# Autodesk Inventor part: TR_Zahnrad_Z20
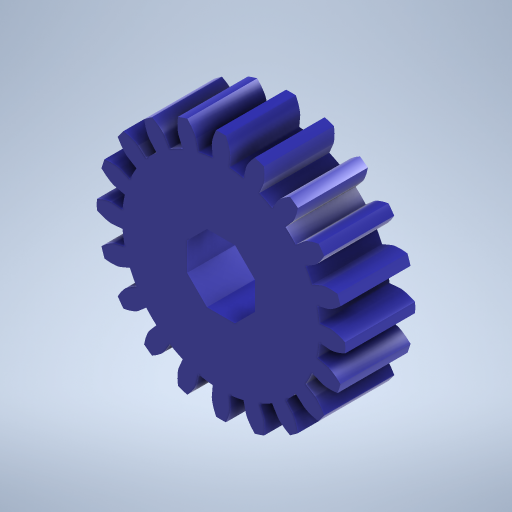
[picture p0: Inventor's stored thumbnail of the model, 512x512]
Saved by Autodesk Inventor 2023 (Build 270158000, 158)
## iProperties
Created: 2023-11
Part Number: TR_Zahnrad_Z20
Material: Generic
Document SubType Name: Modeling
Designer: AdminForWorker
Density: 1 g/cm^3
Appearance: Default
Title: Component1
Author: AdminForWorker
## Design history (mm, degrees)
feature "Body1"
sketch "Skizze1"
  geometry: L1 (3, -1.243)-(1.243, -3); L2 (1.243, -3)-(-1.243, -3); L3 (-1.243, -3)-(-3, -1.243); L4 (-3, -1.243)-(-3, 1.243); L5 (-3, 1.243)-(-1.243, 3); L6 (-1.243, 3)-(1.243, 3); L7 (1.243, 3)-(3, 1.243); L8 (3, 1.243)-(3, -1.243); 2 further points
  constraints: 16 end point, 1 coincident, 1 horizontal, 17 other
  dimensions: "d0" = 6 distance between parallel lines of L8 L4 (= AchteckUmkreis)
extrude "Extrusion1" cut sketch "Skizze1" extent not by distance; stored distance "d1" = 0; taper "d2" = 0 deg
body "Solid1"
other parameters: "Radius" = 2.075 [user parameter], "Fasen" = 0.5 [user parameter], "Dicke" = 0.8 [user parameter], "Breitloch" = 2 [user parameter], "Langloch" = 32 [user parameter], "AchteckUmkreis" = 6 [user parameter; used in 1 equation term], "DAchsAufnahme" = 4.1 [user parameter], "AchsDurchmesser" = 4 [user parameter], "AchsFase" = 0.5 [user parameter]
